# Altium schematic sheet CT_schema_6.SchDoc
size 274 x 160 mm
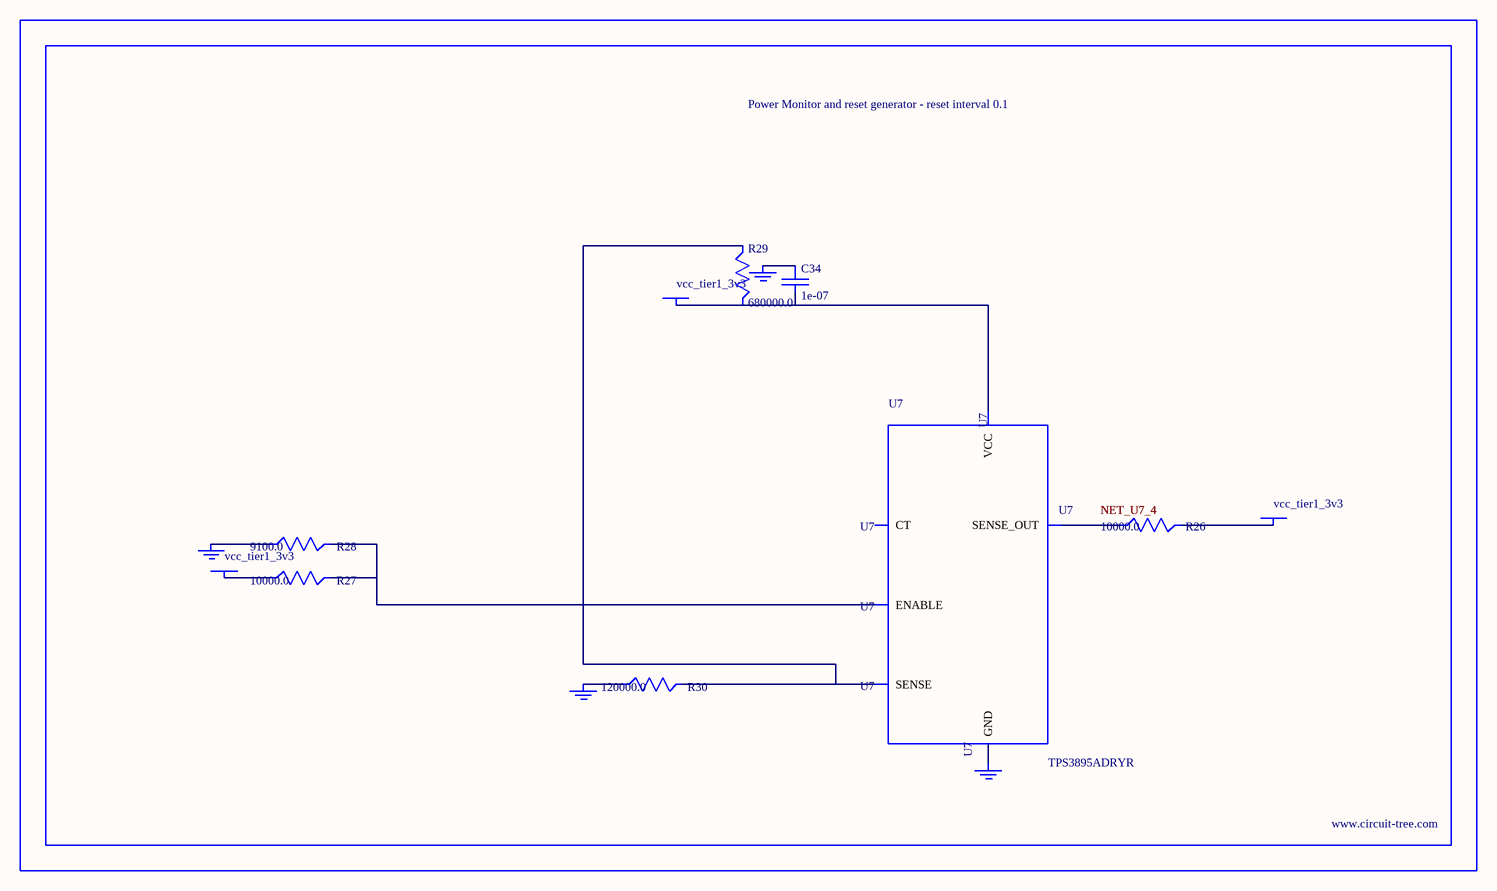
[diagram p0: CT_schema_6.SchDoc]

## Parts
BORDER5  (no value)
C34  1e-07  [C0402]
GND_INSTANCE_5_0  (no value)
GND_INSTANCE_5_1  (no value)
GND_INSTANCE_5_2  (no value)
GND_INSTANCE_5_3  (no value)
POWER_INSTANCE_5_0  vcc_tier1_3v3
POWER_INSTANCE_5_1  vcc_tier1_3v3
POWER_INSTANCE_5_2  vcc_tier1_3v3
R26  10000.0  [R0603]
R27  10000.0  [R0603]
R28  9100.0  [R0603]
R29  680000.0  [R0603]
R30  120000.0  [R0603]
U7  TPS3895ADRYR  [SON-6]

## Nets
NetC34_1: C34.1 GND_INSTANCE_5_2.0(GND)
NetC34_2: C34.2 POWER_INSTANCE_5_2.0(PWR) R29.2 U7.6(VCC)
NetGND_INSTANCE_5_0_0: GND_INSTANCE_5_0.0(GND) R28.1
NetGND_INSTANCE_5_1_0: GND_INSTANCE_5_1.0(GND) R30.1
NetGND_INSTANCE_5_3_0: GND_INSTANCE_5_3.0(GND) U7.2(GND)
NetPOWER_INSTANCE_5_0_0: POWER_INSTANCE_5_0.0(PWR) R27.1
NetPOWER_INSTANCE_5_1_0: POWER_INSTANCE_5_1.0(PWR) R26.2
NetR26_1: R26.1 U7.4(SENSE_OUT)
NetR27_2: R27.2 R28.2 U7.1(ENABLE)
NetR29_1: R29.1 R30.2 U7.3(SENSE)

Not connected (* = marked no-connect by the designer): U7 5(CT)

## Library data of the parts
BORDER5 = BORDER_PAGE5
C34 = C0402C104K3RACTU
GND_INSTANCE_5_0-GND_INSTANCE_5_3 = GND
POWER_INSTANCE_5_0-POWER_INSTANCE_5_2 = PWR
R26 R27 = RC0603JR-0710KL
R28 = RC0603JR-079K1L
R29 = RC0603JR-07680KL
R30 = RC0603JR-07120KL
